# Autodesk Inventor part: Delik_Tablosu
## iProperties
Created: 2005-02
Part Number: Delik_Tablosu
Document SubType Name: Modeling
Designer: Dale Schneider
Density: 1 g/cm^3
Author: Dale Schneider
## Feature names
1. Extrusion1
2. Extrusion2
3. Extrusion3
4. Extrusion4
5. Extrusion5
6. Fillet1
7. Circular Pattern1
8. Extrusion6
9. Fillet2
10. Mirror1
11. Extrusion7
12. Hole1
13. Hole2
14. Mirror3
15. Hole3
16. Hole4
17. Hole5
18. Hole6
19. Mirror2
